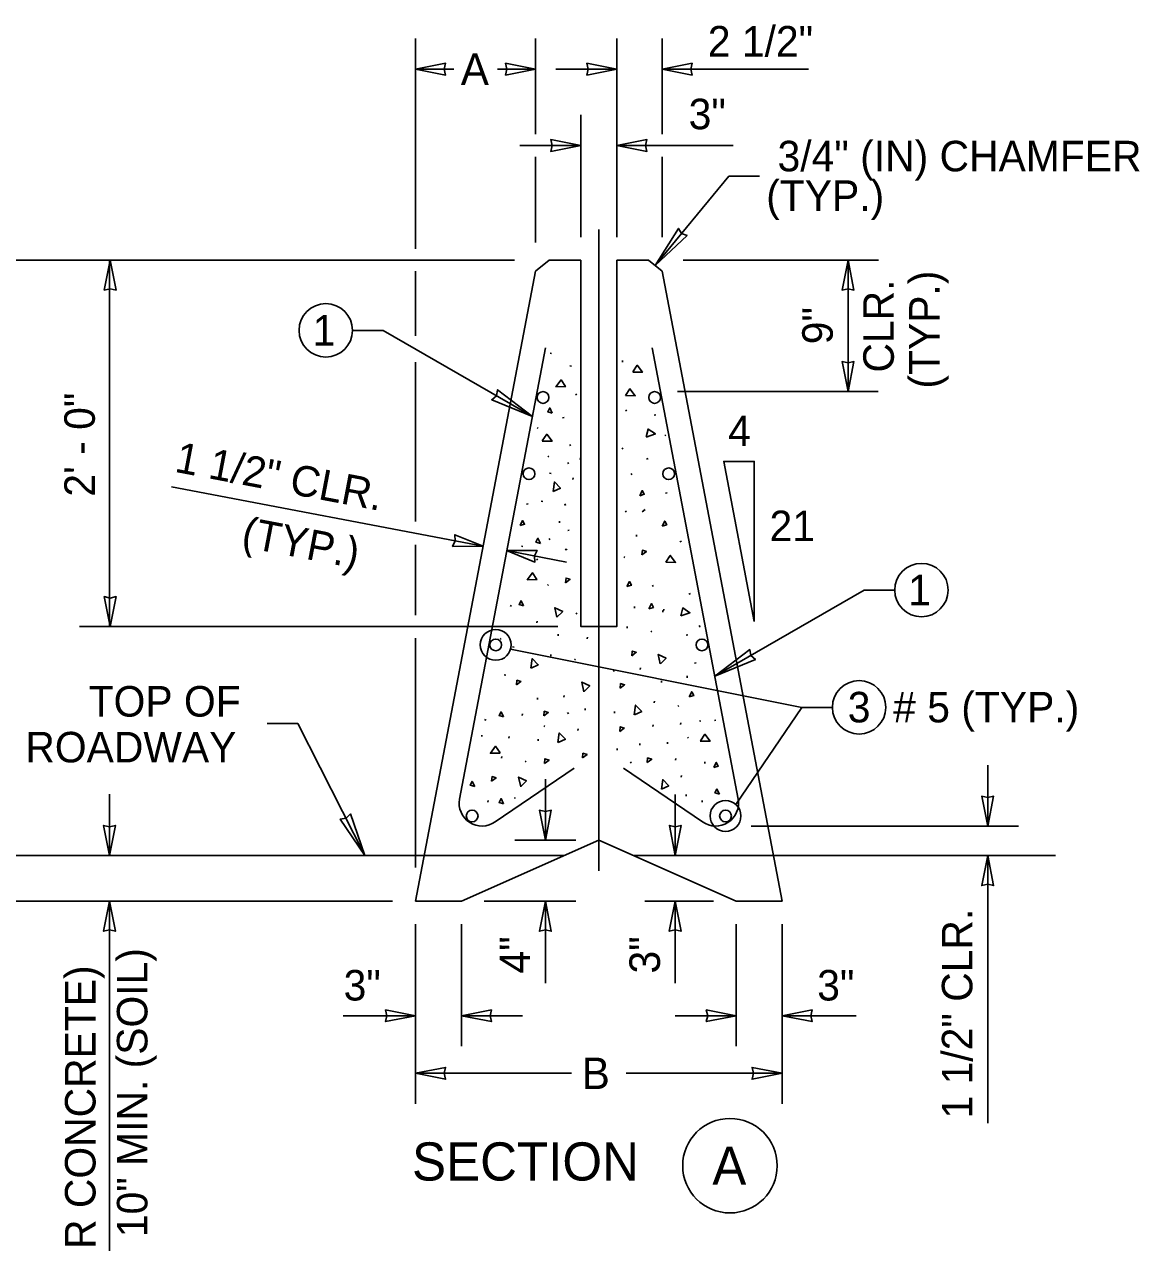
# Model space of a CAD drawing. Extents: x 99862 to 103151, y 100000 to 102076.
# Drawn here: x 100719 to 101303, y 100473 to 101111 of the extents above; entities that cross this region are included whole.
import ezdxf

# ---------------------------------------------------------------- set-up
doc = ezdxf.new("R2010")
doc.units = 0
for name, color, linetype in [('Level 10', 7, 'Continuous'), ('Level 13', 7, 'Continuous'), ('Level 15', 7, 'Continuous'), ('Level 16', 7, 'Continuous'), ('Level 2', 7, 'Continuous'), ('Level 20', 7, 'Continuous'), ('Level 9', 7, 'Continuous')]:
    doc.layers.add(name, color=color, linetype=linetype)

msp = doc.modelspace()

# ---------------------------------------------------------------- linework, layer by layer
at = {"layer": 'Level 10'}
for p, q in [((100991.93, 100941.9), (100946.9, 100705.5)), ((101047.88, 100941.9), (101092.91, 100705.5)), ((100965.57, 100693.55), (101007.04, 100721.75)), ((101074.24, 100693.55), (101032.77, 100721.75))]:
    msp.add_line(p, q, dxfattribs=at)
for centre in [(100990.68, 100915.97), (101049.14, 100915.97), (100983.32, 100875.99), (101056.49, 100875.99), (100965.9, 100786.32), (101073.92, 100786.32), (100953.54, 100696.66), (101086.28, 100696.66)]:
    msp.add_circle(centre, 3.08, dxfattribs=at)
for centre, start, end in [((100958.72, 100703.41), 169.95883, 304.80379), ((101081.09, 100703.41), 235.19621, 10.04117)]:
    msp.add_arc(centre, 12, start, end, dxfattribs=at)
at = {"layer": 'Level 13'}
for p, q in [((100995.19, 100938.94), (100994.35, 100939.16)), ((101005.59, 100932.33), (101004.74, 100932.55)), ((101032.37, 100934.52), (101032.31, 100935.39)), ((101007.82, 100917.88), (101008.18, 100917.16)), ((101034.02, 100909.49), (101034.38, 100908.77)), ((101048.95, 100906.68), (101049.79, 100906.9)), ((100987.57, 100899.76), (100988.04, 100900.19)), ((101000.82, 100905.32), (101001.66, 100905.54)), ((101054.92, 100895.91), (101054.45, 100896.35)), ((101004.75, 100891.27), (101005.11, 100890.55)), ((101032.18, 100889.63), (101032.54, 100888.91)), ((100993.25, 100884.81), (100993.73, 100885.25)), ((101003.73, 100881.86), (101004.09, 100881.14)), ((101010.17, 100883.53), (101010.23, 100884.4)), ((101044.96, 100883.68), (101045.81, 100883.9)), ((100994.89, 100876.08), (100994.05, 100876.31)), ((101036.89, 100876.12), (101037.25, 100875.4)), ((101006.36, 100872.96), (101006.42, 100873.83)), ((100990.56, 100861.37), (100989.71, 100861.6)), ((101054.83, 100865.82), (101055.68, 100866.04)), ((100981.97, 100860.02), (100982.82, 100860.25)), ((101002.09, 100860.16), (101002.45, 100859.44)), ((101033.84, 100856.59), (101034.2, 100855.87)), ((100999.31, 100850.27), (100999.37, 100851.14)), ((101003.6, 100846.23), (101004.44, 100846.46)), ((101039.63, 100843.1), (101039.69, 100843.97)), ((100980.16, 100837.88), (100979.32, 100838.1)), ((100993.87, 100842.04), (100994.23, 100841.32)), ((101002.33, 100836.53), (101002.84, 100836.15)), ((101002.73, 100836.46), (101003.25, 100836.08)), ((101062.33, 100840.39), (101063.18, 100840.61)), ((100987.2, 100830.97), (100987.98, 100831.18)), ((101032.92, 100832.44), (101033.44, 100832.06)), ((100992.95, 100817.89), (100993.47, 100817.51)), ((101048.03, 100817.61), (101048.39, 100816.89)), ((101067.04, 100812.98), (101067.89, 100813.21)), ((100974.23, 100806.69), (100973.38, 100806.92)), ((101038.55, 100805.57), (101038.61, 100806.44)), ((101053.49, 100803.48), (101053.43, 100804.35)), ((101053.81, 100804.12), (101053.88, 100804.99)), ((100987.46, 100797.93), (100987.52, 100798.81)), ((101008.06, 100803.06), (101008.42, 100802.34)), ((100998.57, 100791.02), (100998.63, 100791.89)), ((101034.74, 100795), (101034.8, 100795.87)), ((101047.11, 100793.46), (101047.63, 100793.08)), ((101065.7, 100791.43), (101066.54, 100791.66)), ((101072.87, 100795.96), (101072.4, 100796.4)), ((101073.02, 100795.58), (101072.55, 100796.01)), ((100968.25, 100789.29), (100968.72, 100789.73)), ((100975.57, 100785.15), (100974.73, 100785.37)), ((101013.84, 100789.57), (101013.9, 100790.44)), ((100994.76, 100780.45), (100994.82, 100781.32)), ((101007.14, 100778.91), (101007.65, 100778.53)), ((101027.69, 100772.31), (101027.75, 100773.18)), ((101041.62, 100773.5), (101041.68, 100774.37)), ((101070.03, 100776.72), (101070.88, 100776.95)), ((100971.24, 100770.43), (100970.39, 100770.66)), ((101052.73, 100766.59), (101052.79, 100767.46)), ((101066.11, 100769.14), (101066.17, 100770.02)), ((101001.64, 100758.95), (101001.7, 100759.83)), ((100987.72, 100757.76), (100987.78, 100758.63)), ((101012.76, 100752.04), (101012.82, 100752.91)), ((101048.92, 100756.02), (101048.98, 100756.89)), ((101061.3, 100754.48), (101061.81, 100754.1)), ((100960.84, 100746.94), (100960, 100747.17)), ((100979.78, 100749.4), (100979.84, 100750.27)), ((101003.57, 100750.86), (101003.93, 100750.14)), ((101028.03, 100750.59), (101028.09, 100751.46)), ((101073.39, 100746.32), (101072.61, 100746.53)), ((101080.43, 100746.69), (101081.27, 100746.92)), ((100991.13, 100743.95), (100991.65, 100743.57)), ((101008.95, 100741.47), (101009.01, 100742.34)), ((101048.25, 100743.6), (101048.31, 100744.48)), ((101062.73, 100744.64), (101062.79, 100745.51)), ((100958.62, 100738.23), (100958.68, 100739.1)), ((100972.79, 100737.49), (100972.85, 100738.36)), ((100988.06, 100736.04), (100988.12, 100736.91)), ((101041.33, 100733.71), (101041.39, 100734.59)), ((101055.8, 100734.52), (101055.86, 100735.39)), ((100968.98, 100726.92), (100969.04, 100727.8)), ((101029.53, 100731.09), (101029.59, 100731.97)), ((100981.35, 100725.38), (100981.87, 100725)), ((101036.43, 100725.1), (101036.79, 100724.38)), ((101060.11, 100726), (101060.17, 100726.87)), ((101075.45, 100724.24), (101075.51, 100725.11)), ((101063.11, 100717.04), (101063.17, 100717.91)), ((100961.81, 100703.87), (100961.87, 100704.74)), ((100975.89, 100705.87), (100975.92, 100706.3)), ((101065.67, 100707.13), (101065.61, 100708)), ((101073.97, 100703.87), (101074.03, 100704.74))]:
    msp.add_line(p, q, dxfattribs=at)
for points in [[(101037.65, 100929.31), (101042.77, 100929.21), (101040.02, 100932.86), (101037.69, 100929.38)], [(101002.55, 100921.64), (100997.43, 100921.54), (101000.17, 100925.19), (101002.51, 100921.72)], [(101033.85, 100916.98), (101038.97, 100916.88), (101036.23, 100920.54), (101033.89, 100917.06)], [(100995.49, 100907.8), (100993.13, 100908.51), (100994.17, 100910.47), (100995.49, 100907.8)], [(100990.26, 100893.14), (100995.38, 100893.04), (100992.64, 100896.7), (100990.3, 100893.22)], [(101044.7, 100895.21), (101049.55, 100896.87), (101045.72, 100899.37), (101044.72, 100895.3)], [(100995.92, 100866.61), (100996.62, 100871.68), (100999.8, 100868.4), (100996, 100866.64)], [(101041.31, 100864.51), (101043.67, 100865.22), (101042.63, 100867.18), (101041.31, 100864.51)], [(101044.11, 100857.23), (101042.64, 100856.11)], [(100978.68, 100848.8), (100981.04, 100849.5), (100980, 100851.47), (100978.68, 100848.8)], [(101053.15, 100848.56), (101055.51, 100849.26), (101054.47, 100851.23), (101053.15, 100848.56)], [(100989.35, 100839.51), (100986.99, 100840.22), (100988.02, 100842.18), (100989.35, 100839.51)], [(101042.48, 100833.46), (101042.72, 100835.91), (101044.84, 100835.26), (101042.48, 100833.46)], [(101054.98, 100829.63), (101060.1, 100829.53), (101057.35, 100833.18), (101055.02, 100829.7)], [(100987.52, 100820.58), (100982.4, 100820.48), (100985.14, 100824.13), (100987.48, 100820.66)], [(101002.5, 100818.91), (101002.74, 100821.36), (101004.87, 100820.71), (101002.5, 100818.91)], [(101034.64, 100816.84), (101037, 100817.54), (101035.96, 100819.51), (101034.64, 100816.84)], [(100980.46, 100806.74), (100978.1, 100807.45), (100979.14, 100809.41), (100980.46, 100806.74)], [(100997.92, 100800.76), (100996.85, 100805.77), (101000.96, 100803.78), (100997.99, 100800.82)], [(101046.1, 100805.26), (101048.46, 100805.96), (101047.42, 100807.92), (101046.1, 100805.26)], [(101062.8, 100801.51), (101067.65, 100803.17), (101063.82, 100805.67), (101062.81, 100801.6)], [(100984.32, 100774.1), (100985.02, 100779.17), (100988.2, 100775.89), (100984.4, 100774.13)], [(101037.15, 100780.62), (101037.4, 100783.07), (101039.52, 100782.43), (101037.15, 100780.62)], [(101052.08, 100776.33), (101051.01, 100781.34), (101055.12, 100779.34), (101052.15, 100776.39)], [(100976.72, 100765.38), (100976.96, 100767.83), (100979.08, 100767.18), (100976.72, 100765.38)], [(101012.11, 100761.78), (101011.04, 100766.79), (101015.15, 100764.8), (101012.18, 100761.84)], [(101031.04, 100763.61), (101031.29, 100766.06), (101033.41, 100765.41), (101031.04, 100763.61)], [(101067.28, 100759.08), (101069.64, 100759.78), (101068.61, 100761.74), (101067.28, 100759.08)], [(101038.48, 100749.67), (101039.18, 100754.74), (101042.36, 100751.46), (101038.56, 100749.7)], [(100970.02, 100748.57), (100967.66, 100749.28), (100968.7, 100751.24), (100970.02, 100748.57)], [(100991.07, 100749.06), (100991.31, 100751.51), (100993.44, 100750.86), (100991.07, 100749.06)], [(100998.51, 100735.12), (100999.21, 100740.19), (101002.39, 100736.91), (100998.59, 100735.15)], [(101030.88, 100740.95), (101031.12, 100743.4), (101033.24, 100742.75), (101030.88, 100740.95)], [(101066.83, 100737.9), (101066.34, 100737.41)], [(101073.07, 100735.93), (101078.19, 100735.83), (101075.45, 100739.48), (101073.11, 100736.01)], [(100968.2, 100729.64), (100963.08, 100729.54), (100965.82, 100733.2), (100968.16, 100729.72)], [(101011.37, 100727.09), (101011.61, 100729.54), (101013.74, 100728.9), (101011.37, 100727.09)], [(100991.45, 100724.17), (100991.7, 100726.63), (100993.82, 100725.98), (100991.45, 100724.17)], [(101045.23, 100724.63), (101045.47, 100727.08), (101047.6, 100726.43), (101045.23, 100724.63)], [(101080.13, 100722.09), (101082.49, 100722.8), (101081.45, 100724.76), (101080.13, 100722.09)], [(100954.87, 100712.11), (100952.51, 100712.81), (100953.55, 100714.78), (100954.87, 100712.11)], [(100963.71, 100714.83), (100963.96, 100717.28), (100966.08, 100716.64), (100963.71, 100714.83)], [(100978.96, 100712.02), (100977.88, 100717.03), (100981.99, 100715.03), (100979.02, 100712.07)], [(101052.67, 100710.69), (101053.37, 100715.76), (101056.55, 100712.48), (101052.75, 100710.72)], [(101083.07, 100708.11), (101080.71, 100708.82), (101081.75, 100710.78), (101083.07, 100708.11)], [(100970.02, 100703.08), (100967.66, 100703.79), (100968.7, 100705.75), (100970.02, 100703.08)]]:
    msp.add_lwpolyline(points, dxfattribs=at)
at = {"layer": 'Level 15'}
for p, q in [((100923.91, 101103.98), (100923.91, 100993.83)), ((100986.78, 101053.98), (100986.78, 101103.98)), ((101029.38, 100999.98), (101029.38, 101103.98)), ((101053.04, 101053.98), (101053.04, 101103.99)), ((100943.91, 101087.98), (100923.91, 101087.98)), ((100986.78, 101087.98), (100966.78, 101087.98)), ((101029.38, 101087.98), (100997.38, 101087.98)), ((101053.03, 101087.99), (101129.77, 101087.99)), ((101010.44, 100999.98), (101010.44, 101063.98)), ((101010.44, 101047.98), (100978.44, 101047.98)), ((101029.38, 101047.98), (101090.29, 101047.98)), ((100986.78, 100997.23), (100986.78, 101041.98)), ((101053.04, 100999.98), (101053.04, 101041.98)), ((101087.98, 101031.98), (101049.48, 100985.04)), ((101087.98, 101031.98), (101103.98, 101031.98)), ((101019.91, 101003.98), (101019.91, 100667.98)), ((100975.69, 100987.98), (100591.9, 100987.96)), ((100763.56, 100795.88), (100763.56, 100987.97)), ((101064.12, 100987.97), (101166.43, 100987.97)), ((101150.43, 100987.97), (101150.43, 100919.05)), ((100923.91, 100982.21), (100923.91, 100948.23)), ((100890.88, 100951.14), (100906.88, 100951.14)), ((100985.11, 100905.97), (100906.88, 100951.14)), ((100923.91, 100934.38), (100923.91, 100850.91)), ((101061.14, 100919.05), (101166.23, 100919.05)), ((100959.34, 100838.05), (100796.01, 100869.16)), ((100923.91, 100838.69), (100923.91, 100801.88)), ((101002.98, 100829.74), (100971.54, 100835.73)), ((101080.65, 100769.88), (101158.88, 100815.05)), ((101174.88, 100815.05), (101158.88, 100815.05)), ((100998.44, 100795.88), (100747.91, 100795.88)), ((100923.91, 100789.88), (100923.91, 100669.67)), ((101126.23, 100753.59), (101142.23, 100753.59)), ((100862.2, 100745.17), (100846.2, 100745.17)), ((100897.33, 100675.98), (100862.2, 100745.17)), ((101223.61, 100691.28), (101223.61, 100723.28)), ((100991.9, 100683.98), (100991.9, 100715.98)), ((100763.56, 100675.98), (100763.56, 100708.12)), ((101059.94, 100675.98), (101059.94, 100707.98)), ((101099.62, 100691.28), (101239.75, 100691.28)), ((101007.9, 100683.98), (100975.9, 100683.98)), ((101223.59, 100675.89), (101223.59, 100535.66)), ((100911.9, 100651.98), (100591.91, 100651.98)), ((100763.56, 100263.53), (100763.56, 100651.98)), ((100959.9, 100651.98), (101007.89, 100651.98)), ((100991.9, 100651.98), (100991.9, 100609)), ((101043.92, 100651.98), (101079.91, 100651.98)), ((101059.91, 100651.98), (101059.91, 100609)), ((100923.91, 100639.98), (100923.91, 100545.84)), ((100947.9, 100639.98), (100947.9, 100575.98)), ((101091.91, 100639.98), (101091.91, 100575.98)), ((101115.91, 100639.98), (101115.91, 100545.84)), ((100923.91, 100591.98), (100886.05, 100591.98)), ((100947.9, 100591.98), (100979.9, 100591.98)), ((101091.92, 100591.98), (101059.92, 100591.98)), ((101115.91, 100591.98), (101154.68, 100591.98)), ((101005.66, 100561.84), (100923.9, 100561.84)), ((101115.91, 100561.84), (101034.16, 100561.84))]:
    msp.add_line(p, q, dxfattribs=at)
for points in [[(100923.91, 101087.98), (100939.63, 101084.9), (100938.9, 101087.98), (100939.63, 101091.07)], [(100986.78, 101087.98), (100971.05, 101091.07), (100971.78, 101087.98), (100971.05, 101084.9)], [(101029.38, 101087.98), (101013.65, 101091.07), (101014.38, 101087.98), (101013.65, 101084.9)], [(101053.03, 101087.99), (101068.76, 101084.9), (101068.03, 101087.99), (101068.76, 101091.07)], [(101010.44, 101047.98), (100994.71, 101051.07), (100995.44, 101047.98), (100994.71, 101044.9)], [(101029.38, 101047.98), (101045.1, 101044.9), (101044.37, 101047.98), (101045.1, 101051.07)], [(101049.33, 100985.04), (101061.56, 101004.55), (101063.19, 101001.83), (101066.16, 101000.75)], [(100763.91, 100987.97), (100760.82, 100972.24), (100763.91, 100972.97), (100766.99, 100972.24)], [(101150.43, 100987.97), (101147.35, 100972.24), (101150.43, 100972.97), (101153.52, 100972.24)], [(101150.43, 100919.05), (101147.35, 100934.78), (101150.43, 100934.05), (101153.52, 100934.78)], [(100985.11, 100905.97), (100966.84, 100919.97), (100966.26, 100916.85), (100963.85, 100914.8)], [(100959.34, 100838.05), (100943.32, 100837.96), (100944.61, 100840.86), (100944.47, 100844.02)], [(100971.54, 100835.73), (100987.57, 100835.81), (100986.27, 100832.92), (100986.41, 100829.75)], [(100763.91, 100795.88), (100760.82, 100811.61), (100763.91, 100810.88), (100766.99, 100811.61)], [(101080.65, 100769.89), (101098.92, 100783.88), (101099.5, 100780.77), (101101.91, 100778.71)], [(101223.61, 100691.28), (101226.7, 100707), (101223.61, 100706.27), (101220.53, 100707)], [(100897.33, 100675.98), (100889.78, 100697.73), (100887.58, 100695.45), (100884.44, 100695.06)], [(100991.9, 100683.98), (100994.98, 100699.71), (100991.9, 100698.98), (100988.82, 100699.71)], [(100763.56, 100675.98), (100760.48, 100691.71), (100763.56, 100690.98), (100766.65, 100691.71)], [(101059.94, 100675.98), (101063.02, 100691.71), (101059.94, 100690.98), (101056.85, 100691.71)], [(101223.59, 100675.89), (101226.68, 100660.17), (101223.59, 100660.9), (101220.51, 100660.17)], [(100763.56, 100651.98), (100760.48, 100636.26), (100763.56, 100636.99), (100766.65, 100636.26)], [(100991.9, 100651.98), (100994.98, 100636.26), (100991.9, 100636.99), (100988.82, 100636.26)], [(101059.91, 100651.98), (101063, 100636.26), (101059.91, 100636.99), (101056.83, 100636.26)], [(100923.91, 100591.98), (100908.19, 100595.07), (100908.91, 100591.98), (100908.19, 100588.9)], [(100947.9, 100591.98), (100963.62, 100588.9), (100962.9, 100591.98), (100963.62, 100595.07)], [(101091.92, 100591.98), (101076.19, 100595.07), (101076.92, 100591.98), (101076.19, 100588.9)], [(101115.91, 100591.98), (101131.64, 100595.07), (101130.91, 100591.98), (101131.64, 100588.9)], [(100923.91, 100561.84), (100939.64, 100558.75), (100938.91, 100561.84), (100939.64, 100564.92)], [(101115.91, 100561.84), (101100.19, 100564.92), (101100.92, 100561.84), (101100.19, 100558.75)]]:
    msp.add_lwpolyline(points, close=True, dxfattribs=at)
for points in [[(101101.3, 100798.5), (101101.3, 100882.5), (101085.3, 100882.5), (101101.3, 100798.5)], [(100973.68, 100784.14), (101126.23, 100753.59), (101091.66, 100702.69)]]:
    msp.add_lwpolyline(points, dxfattribs=at)
for centre in [(100965.9, 100786.32), (101086.28, 100696.66)]:
    msp.add_circle(centre, 8.08, dxfattribs=at)
at = {"layer": 'Level 16'}
for p, q in [((100866.17, 100675.98), (100928.47, 100675.98)), ((101173.64, 100675.98), (101111.34, 100675.98))]:
    msp.add_line(p, q, dxfattribs=at)
for points in [[(100928.47, 100675.98), (100663.43, 100675.98)], [(101111.34, 100675.98), (101259.19, 100675.98)]]:
    msp.add_lwpolyline(points, dxfattribs=at)
at = {"layer": 'Level 2'}
for p, q in [((100986.78, 100982.09), (100993.9, 100987.98)), ((100993.9, 100987.98), (101010.44, 100987.98)), ((101029.38, 100987.98), (101045.91, 100987.98)), ((101045.91, 100987.98), (101053.04, 100982.09)), ((100923.9, 100651.98), (100986.78, 100982.09)), ((101053.04, 100982.09), (101115.91, 100651.98)), ((101019.9, 100683.98), (100947.9, 100651.98)), ((101019.91, 100683.98), (101019.9, 100683.98)), ((101091.91, 100651.98), (101019.91, 100683.98)), ((101001.9, 100675.98), (100928.47, 100675.98)), ((101111.34, 100675.98), (101037.91, 100675.98)), ((100947.9, 100651.98), (100923.9, 100651.98)), ((101115.91, 100651.98), (101091.91, 100651.98))]:
    msp.add_line(p, q, dxfattribs=at)
for points in [[(101010.44, 100987.98), (101010.44, 100795.98), (101022.44, 100795.98)], [(101017.38, 100795.98), (101029.38, 100795.98), (101029.38, 100987.98)]]:
    msp.add_lwpolyline(points, dxfattribs=at)
at = {"layer": 'Level 20'}
for centre in [(100876.88, 100951.14), (101188.88, 100815.05), (101156.23, 100753.59)]:
    msp.add_circle(centre, 14, dxfattribs=at)
at = {"layer": 'Level 9'}
msp.add_circle((101088.58, 100513.41), 24.75, dxfattribs=at)

# ---------------------------------------------------------------- texts
at = {"layer": 'Level 15'}
for s, p in [('A', (100947.6, 101079.73)), ('B', (101010.97, 100553.59))]:
    msp.add_text(s, height=16.5, dxfattribs=at).set_placement(p)
at = {"layer": 'Level 20'}
for s, height, p in [('2 1/2"', 16, (101076.99, 101094.62)), (' 3/4" (IN) CHAMFER', 16, (101107.58, 101034.45)), ('(TYP.)', 16, (101107.58, 101013.74)), ('1', 16, (100870.01, 100943.14)), ('4', 16, (101087.63, 100890.5)), ('21', 16, (101109.32, 100840.67)), ('1', 16, (101181.93, 100807.05)), (' 3  # 5 (TYP.)', 16, (101144.35, 100745.7)), ('3"', 16, (100886.22, 100599.98)), ('SECTION', 20, (100922.05, 100505.64)), ('A', 20, (101079.34, 100503.41))]:
    msp.add_text(s, height=height, dxfattribs=at).set_placement(p)
for s, rotation, p in [('3"', 360, (101066.96, 101056.51)), ('(TYP.)', 90, (101198.43, 100920.62)), ('CLR.', 90, (101174.43, 100929.02)), ('9"', 90, (101142.43, 100943.85)), ('2\' - 0"', 90, (100755.91, 100863.99)), ('1 1/2" CLR.    ', 349.21603, (100797.21, 100877.08)), ('       (TYP.)', 349.21603, (100791.22, 100845.64)), ('TOP OF', 360, (100752.65, 100748.75)), ('ROADWAY', 360, (100719.5, 100724.75)), ('1 1/2" CLR. ', 90, (101215.59, 100538.18)), ('4"', 90, (100983.91, 100614.12)), ('3"', 90, (101051.92, 100614.12)), ('10" MIN. (SOIL)', 90, (100783.45, 100475.98)), ('3" MIN. (ASPHALT OR CONCRETE)', 90, (100756.25, 100266.04)), ('3"', 360, (101134.29, 100599.98))]:
    msp.add_text(s, height=16, rotation=rotation, dxfattribs=at).set_placement(p)

doc.saveas('drawing.dxf')
